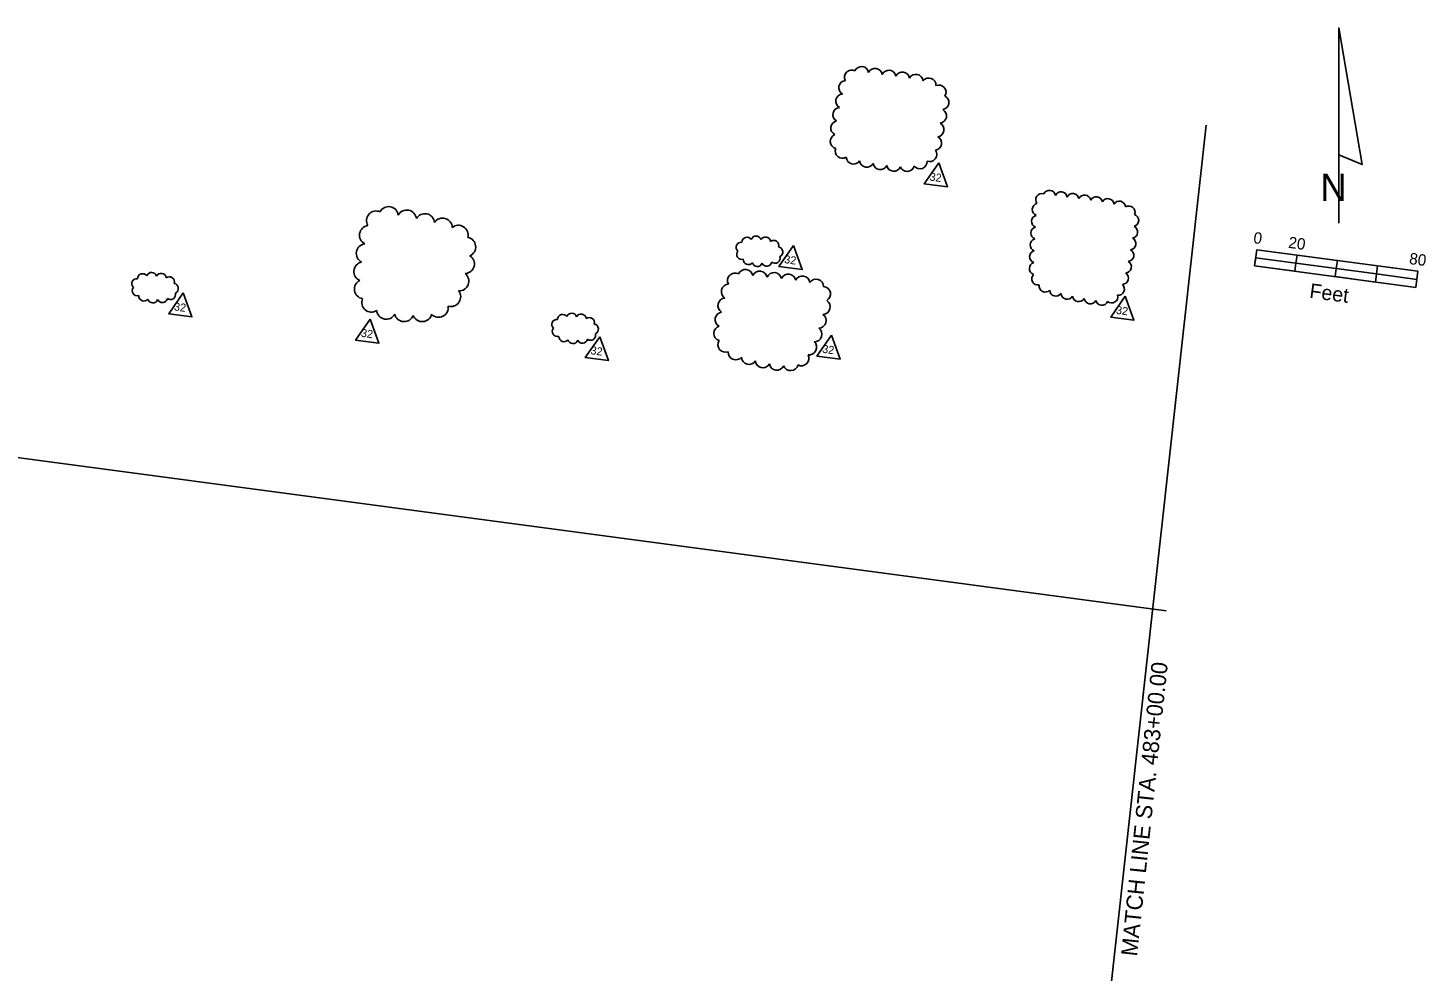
# Model space of a CAD drawing. Extents: x 925493 to 926837, y 636307 to 637171.
# Drawn here: x 926150 to 926837, y 636631 to 637095 of the extents above; entities that cross this region are included whole.
import ezdxf

# ---------------------------------------------------------------- set-up
doc = ezdxf.new("R2010")
doc.units = 0
for name, color, linetype in [('ActivePointCell_dp', 7, 'Continuous'), ('Cloud_dp', 7, 'Continuous'), ('MatchLines_dp', 7, 'Continuous'), ('NorthArw_dp', 7, 'Continuous'), ('Scale_dp', 7, 'Continuous')]:
    doc.layers.add(name, color=color, linetype=linetype)

msp = doc.modelspace()

# ---------------------------------------------------------------- linework, layer by layer
at = {"layer": 'ActivePointCell_dp'}
msp.add_line((926709.43, 636807.88), (925632.34, 636951.66), dxfattribs=at)
at = {"layer": 'Cloud_dp'}
for points in [[(926597.65, 637028.24), (926590.46, 637017.98), (926601.91, 637016.45)], [(926526.16, 636987.6), (926518.96, 636977.33), (926530.42, 636975.8)], [(926225.94, 636964.34), (926218.74, 636954.08), (926230.19, 636952.55)], [(926689.41, 636962.65), (926682.21, 636952.39), (926693.67, 636950.86)], [(926317.91, 636951.36), (926310.71, 636941.1), (926322.16, 636939.57)], [(926544.84, 636943.5), (926537.65, 636933.24), (926549.1, 636931.71)], [(926430.86, 636942.79), (926423.66, 636932.53), (926435.11, 636931)]]:
    msp.add_lwpolyline(points, close=True, dxfattribs=at)
for centre, radius, start, end in [((926554.8, 637070.46), 3.55, 63.21957, 208.21957), ((926559.62, 637072.13), 3.55, 9.89674, 154.89674), ((926566.33, 637071.23), 3.55, 9.89674, 154.89674), ((926573.05, 637070.33), 3.55, 9.89674, 154.89674), ((926551.98, 637065.25), 3.55, 94.86217, 239.86217), ((926579.76, 637069.43), 3.55, 9.7329, 154.7329), ((926586.37, 637068.31), 3.55, 6.07576, 151.07576), ((926592.7, 637066.5), 3.55, 357.00805, 142.00805), ((926550.49, 637058.64), 3.55, 94.86217, 239.86217), ((926597.65, 637063.05), 3.55, 328.28132, 113.28132), ((926599.06, 637058.02), 3.55, 278.19302, 63.19302), ((926549.09, 637052.03), 3.55, 96.19148, 241.19148), ((926597.87, 637051.38), 3.55, 276.44011, 61.44011), ((926548.02, 637045.43), 3.55, 100.27464, 245.27464), ((926596.66, 637044.69), 3.55, 278.08273, 63.08273), ((926547.8, 637038.88), 3.55, 110.87796, 255.87796), ((926595.51, 637038.03), 3.55, 277.28752, 62.28752), ((926550.22, 637034.1), 3.55, 157.78535, 302.78535), ((926593.07, 637032.45), 3.55, 250.35783, 35.35783), ((926555.69, 637031.23), 3.55, 181.96225, 326.96225), ((926562.19, 637029.71), 3.55, 186.63574, 331.63574), ((926568.83, 637028.57), 3.55, 188.89439, 333.89439), ((926575.49, 637027.75), 3.55, 192.06993, 337.06993), ((926582.08, 637027.62), 3.55, 200.69985, 345.69985), ((926588.33, 637028.93), 3.55, 217.89904, 2.89904), ((926648.36, 637010.15), 3.05, 72.40624, 217.40624), ((926652.04, 637011.75), 3.05, 9.62007, 154.62007), ((926657.81, 637010.97), 3.05, 9.81026, 154.81026), ((926663.58, 637010.19), 3.05, 9.86038, 154.86038), ((926669.36, 637009.42), 3.05, 9.88707, 154.88707), ((926675.11, 637008.61), 3.05, 9.1767, 154.1767), ((926327, 637002.02), 4.76, 7.41413, 152.41413), ((926335.9, 637000.34), 4.76, 6.21934, 151.21934), ((926646.67, 637005.34), 3.05, 103.97344, 248.97344), ((926680.82, 637007.67), 3.05, 7.13679, 152.13679), ((926686.44, 637006.43), 3.05, 2.95146, 147.95146), ((926691.14, 637004.02), 3.05, 337.6348, 122.6348), ((926320.84, 636999.88), 4.76, 66.0508, 211.0508), ((926344.79, 636998.54), 4.76, 5.8038, 150.8038), ((926353.49, 636996.37), 4.76, 1.17521, 146.17521), ((926646.31, 636999.52), 3.05, 103.97344, 248.97344), ((926692.94, 636999.98), 3.05, 285.38352, 70.38352), ((926317.38, 636992.7), 4.76, 97.40858, 242.40858), ((926361.33, 636992.83), 4.76, 345.32915, 130.32915), ((926365.03, 636986.95), 4.76, 294.01796, 79.01796), ((926503.29, 636989.18), 2.51, 34.10765, 179.10765), ((926507.76, 636989.8), 2.51, 16.71694, 161.71694), ((926512.38, 636989.34), 2.51, 6.96113, 151.96113), ((926645.96, 636993.71), 3.05, 104.07267, 249.07267), ((926691.57, 636988.55), 3.05, 277.79217, 62.79217), ((926692.44, 636994.27), 3.05, 279.75907, 64.75907), ((926315.8, 636983.75), 4.76, 97.60686, 242.60686), ((926500.45, 636986.72), 2.51, 82.67056, 227.67056), ((926500.72, 636983.29), 2.51, 141.30835, 286.30835), ((926516.42, 636987.66), 2.51, 342.91745, 127.91745), ((926518.38, 636984.45), 2.51, 294.76198, 79.76198), ((926645.37, 636982.1), 3.05, 105.28827, 250.28827), ((926645.63, 636987.91), 3.05, 104.51964, 249.51964), ((926690.53, 636982.84), 3.05, 276.68228, 61.68228), ((926314.64, 636974.87), 4.76, 102.46011, 247.46011), ((926364.4, 636978.59), 4.76, 272.32491, 57.32491), ((926503.94, 636980.73), 2.51, 176.73132, 321.73132), ((926508.34, 636979.81), 2.51, 194.62704, 339.62704), ((926513, 636979.96), 2.52, 203.8708, 348.8708), ((926517.03, 636981.44), 2.51, 231.69605, 16.69605), ((926645.24, 636976.31), 3.05, 107.05687, 252.05687), ((926689.35, 636977.16), 3.05, 274.83714, 59.83714), ((926203.07, 636968.81), 2.51, 82.67056, 227.67056), ((926205.9, 636971.27), 2.51, 34.10765, 179.10765), ((926210.37, 636971.89), 2.51, 16.71694, 161.71694), ((926215, 636971.43), 2.51, 6.96113, 151.96113), ((926219.04, 636969.75), 2.51, 342.91745, 127.91745), ((926314.89, 636966.19), 4.76, 115.92357, 260.92357), ((926361.66, 636970.08), 4.76, 267.03467, 52.03467), ((926497.4, 636970.38), 3.71, 62.54759, 207.54759), ((926502.49, 636972.16), 3.71, 10.89854, 155.89854), ((926509.52, 636971.37), 3.71, 11.315, 156.315), ((926516.55, 636970.62), 3.71, 11.42917, 156.42917), ((926523.58, 636969.85), 3.71, 11.15655, 156.15655), ((926530.53, 636968.92), 3.71, 8.51094, 153.51094), ((926537.28, 636967.4), 3.71, 1.21361, 146.21361), ((926646.43, 636971.23), 3.05, 134.47336, 279.47336), ((926687.91, 636971.59), 3.05, 271.16569, 56.16569), ((926203.34, 636965.38), 2.51, 141.30835, 286.30835), ((926219.64, 636963.54), 2.51, 231.69605, 16.69605), ((926221, 636966.54), 2.51, 294.76198, 79.76198), ((926357.66, 636962.39), 4.76, 252.89714, 37.89714), ((926494.35, 636964.97), 3.71, 93.72428, 238.72428), ((926540.67, 636963.79), 3.7, 300.15734, 85.15734), ((926649.96, 636967.78), 3.05, 171.73716, 316.73716), ((926655.24, 636965.73), 3.05, 180.8504, 325.8504), ((926660.8, 636964.27), 3.05, 184.72403, 329.72403), ((926685.94, 636966.25), 3.05, 263.39885, 48.39885), ((926206.55, 636962.83), 2.51, 176.73132, 321.73132), ((926210.96, 636961.91), 2.51, 194.62704, 339.62704), ((926215.62, 636962.05), 2.52, 203.8708, 348.8708), ((926318.54, 636959.64), 4.76, 157.28181, 302.28181), ((926351.55, 636957.1), 4.76, 223.93476, 8.93476), ((926492.7, 636958.11), 3.71, 94.24642, 239.24642), ((926540.52, 636957.48), 3.71, 272.08928, 57.08928), ((926666.48, 636963.05), 3.05, 186.12048, 331.12048), ((926672.17, 636962), 3.05, 187.97733, 332.97733), ((926677.88, 636961.26), 3.05, 192.17845, 337.17845), ((926682.65, 636962.42), 3.05, 230.15288, 15.15288), ((926325.82, 636956.13), 4.76, 186.19315, 331.19315), ((926334.62, 636954.95), 4.76, 193.52165, 338.52165), ((926343.49, 636954.93), 4.76, 201.22427, 346.22427), ((926409.73, 636948.79), 2.51, 82.67056, 227.67056), ((926412.57, 636951.25), 2.51, 34.10765, 179.10765), ((926417.04, 636951.87), 2.51, 16.71694, 161.71694), ((926421.67, 636951.41), 2.51, 6.96113, 151.96113), ((926425.71, 636949.73), 2.51, 342.91745, 127.91745), ((926491.31, 636951.25), 3.71, 97.83259, 242.83259), ((926538.56, 636950.71), 3.71, 270.68784, 55.68784), ((926410, 636945.36), 2.51, 141.30835, 286.30835), ((926413.22, 636942.81), 2.51, 176.73132, 321.73132), ((926426.31, 636943.51), 2.51, 231.69605, 16.69605), ((926427.66, 636946.52), 2.51, 294.76198, 79.76198), ((926490.7, 636944.41), 3.71, 106.97085, 251.97085), ((926536.42, 636944.01), 3.71, 268.79302, 53.79302), ((926417.63, 636941.89), 2.51, 194.62704, 339.62704), ((926422.28, 636942.03), 2.52, 203.8708, 348.8708), ((926492.65, 636938.85), 3.71, 146.75924, 291.75924), ((926533.85, 636937.56), 3.71, 262.71171, 47.71171), ((926497.72, 636935.09), 3.71, 175.07021, 320.07021), ((926504.27, 636932.86), 3.71, 182.26282, 327.26282), ((926511.07, 636931.22), 3.71, 185.73723, 330.73723), ((926517.96, 636930.04), 3.71, 189.81758, 334.81758), ((926530.09, 636932.18), 3.71, 242.39107, 27.39107), ((926524.77, 636929.8), 3.71, 201.02318, 346.02318)]:
    msp.add_arc(centre, radius, start, end, dxfattribs=at)
at = {"layer": 'MatchLines_dp'}
msp.add_line((926729.16, 637046.86), (926667.8, 636491.42), dxfattribs=at)
at = {"layer": 'NorthArw_dp'}
msp.add_line((926794.48, 636998.67), (926794.48, 637094.67), dxfattribs=at)
msp.add_lwpolyline([(926794.48, 637032.27), (926794.48, 637094.67), (926806, 637027.47)], close=True, dxfattribs=at)
at = {"layer": 'Scale_dp'}
for p, q in [((926754.08, 636985.55), (926753.02, 636977.62)), ((926833.38, 636974.97), (926754.08, 636985.55)), ((926753.02, 636977.62), (926832.32, 636967.04)), ((926832.32, 636967.04), (926833.38, 636974.97))]:
    msp.add_line(p, q, dxfattribs=at)
for points in [[(926753.02, 636977.62), (926753.55, 636981.59), (926773.37, 636978.94), (926772.84, 636974.97)], [(926773.37, 636978.94), (926773.9, 636982.9), (926793.73, 636980.26), (926793.2, 636976.29)], [(926813.02, 636973.65), (926813.55, 636977.61), (926833.38, 636974.97), (926832.85, 636971)], [(926792.67, 636972.33), (926793.2, 636976.29), (926813.02, 636973.65), (926812.49, 636969.68)]]:
    msp.add_lwpolyline(points, close=True, dxfattribs=at)

# ---------------------------------------------------------------- texts
at = {"layer": 'Cloud_dp'}
for p in [(926592.92, 637019.64), (926521.42, 636979), (926221.2, 636955.75), (926684.67, 636954.05), (926313.17, 636942.77), (926426.12, 636934.19), (926540.11, 636934.91)]:
    msp.add_text('32', height=3.938, rotation=352.39674, dxfattribs=at).set_placement(p)
at = {"layer": 'MatchLines_dp'}
msp.add_text('MATCH LINE STA. 483+00.00', height=8, rotation=84.0095, dxfattribs=at).set_placement((926695.2, 636637.71))
at = {"layer": 'NorthArw_dp'}
msp.add_text('N', height=13.43, dxfattribs=at).set_placement((926785.35, 637009.54))
at = {"layer": 'Scale_dp'}
for s, height, p in [('0', 5.6, (926752.17, 636988.83)), ('20', 5.6, (926769.38, 636986.53)), ('80', 5.6, (926828.83, 636978.6)), ('Feet', 7.2, (926779.72, 636961.95))]:
    msp.add_text(s, height=height, rotation=352.39674, dxfattribs=at).set_placement(p)

doc.saveas('drawing.dxf')
